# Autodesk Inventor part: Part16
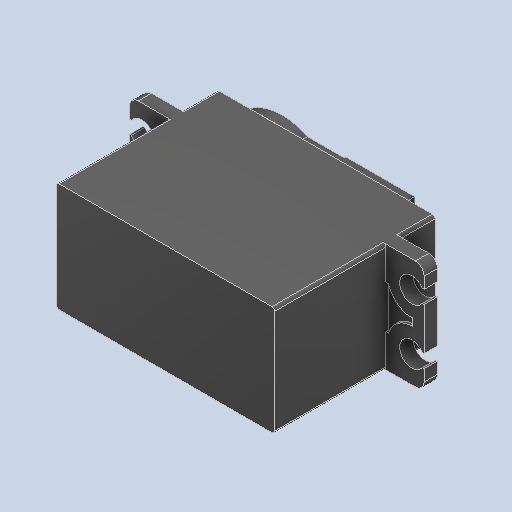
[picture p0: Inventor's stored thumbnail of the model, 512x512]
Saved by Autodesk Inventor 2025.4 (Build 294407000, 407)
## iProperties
Created: 2026-09
Part Number: Part16
Material: Generic
Document SubType Name: Modeling
Designer: AdminForWorker
Density: 1 g/cm^3
Appearance: Default
Author: AdminForWorker
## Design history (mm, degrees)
feature "Body1"
body "Solid1"
